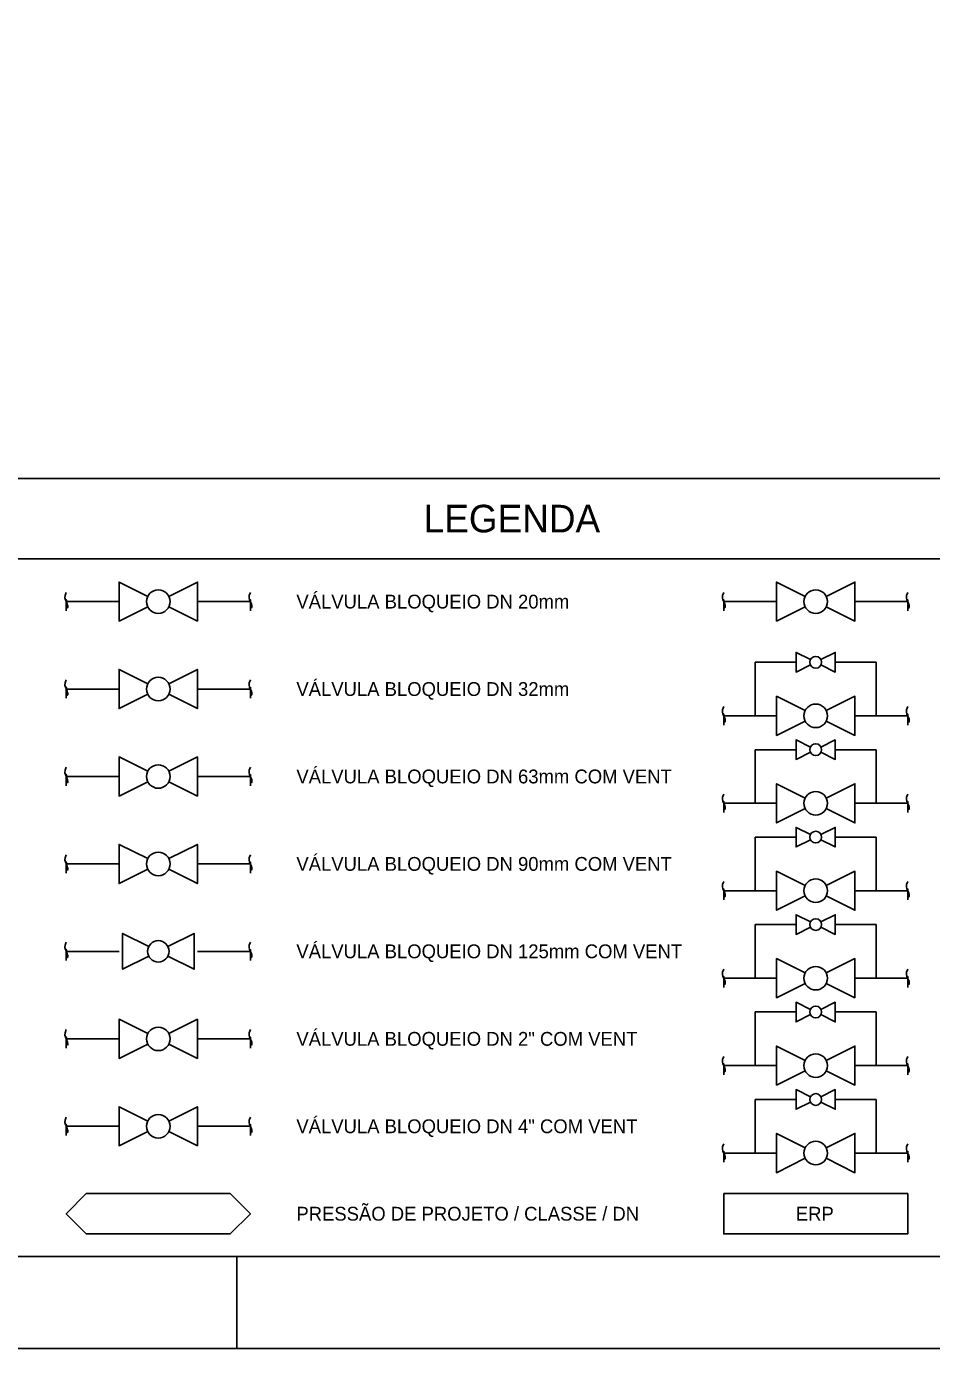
# Model space of a CAD drawing. Extents: x 0 to 841, y 0 to 594.
# Drawn here: x 317.6 to 416, y 0 to 143.7 of the extents above; entities that cross this region are included whole.
import ezdxf

# ---------------------------------------------------------------- set-up
doc = ezdxf.new("R2010")
doc.units = 0
for name, color, linetype in [('FORMATO', 7, 'Continuous'), ('LEGENDA', 7, 'Continuous'), ('MEIO_FIO_GUIA', 7, 'Continuous'), ('SIMBOLO', 7, 'Continuous'), ('VALVULA_ACO_10', 7, 'Continuous'), ('VALVULA_ACO_12', 7, 'Continuous'), ('VALVULA_ACO_14', 7, 'Continuous'), ('VALVULA_ACO_16', 7, 'Continuous'), ('VALVULA_ACO_18', 7, 'Continuous'), ('VALVULA_ACO_2', 7, 'Continuous'), ('VALVULA_ACO_4', 7, 'Continuous'), ('VALVULA_ACO_6', 7, 'Continuous'), ('VALVULA_ACO_8', 7, 'Continuous'), ('VALVULA_PEAD_125', 7, 'Continuous'), ('VALVULA_PEAD_20', 7, 'Continuous'), ('VALVULA_PEAD_32', 7, 'Continuous'), ('VALVULA_PEAD_63', 7, 'Continuous'), ('VALVULA_PEAD_90', 7, 'Continuous')]:
    doc.layers.add(name, color=color, linetype=linetype)

# ---------------------------------------------------------------- blocks, each defined once
blk = doc.blocks.new('VB63')
at = {"layer": 'VALVULA_PEAD_63'}
for points in [[(-1018.223773, 347.405131), (-1021.335533, 345.849251), (-1021.335533, 350.102196), (-1018.223773, 348.546316)], [(-1015.941403, 347.405131), (-1012.829643, 345.849251), (-1012.829643, 350.102196), (-1015.941403, 348.546316)]]:
    blk.add_lwpolyline(points, dxfattribs=at)
blk.add_circle((-1017.082588, 347.975723), 1.275883, dxfattribs=at)
for start, end in [(0, 180), (180, 0)]:
    blk.add_arc((-1017.082588, 347.975723), 1.275883, start, end, dxfattribs=at)
blk = doc.blocks.new('VB125')
at = {"layer": 'VALVULA_PEAD_125'}
for points in [[(-0.347922, -0.173961), (-1.296629, -0.648315), (-1.296629, 0.648315), (-0.347922, 0.173961)], [(0.347922, -0.173961), (1.296629, -0.648315), (1.296629, 0.648315), (0.347922, 0.173961)]]:
    blk.add_lwpolyline(points, dxfattribs=at)
blk.add_circle((0, 0), 0.388989, dxfattribs=at)
for start, end in [(0, 180), (180, 0)]:
    blk.add_arc((0, 0), 0.388989, start, end, dxfattribs=at)
blk = doc.blocks.new('VB DN2')
at = {"layer": 'VALVULA_ACO_2'}
for points in [[(-1.141185, -0.570592), (-4.252945, -2.126472), (-4.252945, 2.126472), (-1.141185, 0.570592)], [(1.141185, -0.570592), (4.252945, -2.126472), (4.252945, 2.126472), (1.141185, 0.570592)]]:
    blk.add_lwpolyline(points, dxfattribs=at)
blk.add_circle((0, 0), 1.275883, dxfattribs=at)
for start, end in [(0, 180), (180, 0)]:
    blk.add_arc((0, 0), 1.275883, start, end, dxfattribs=at)

msp = doc.modelspace()

# ---------------------------------------------------------------- linework, layer by layer
at = {"layer": 'FORMATO'}
for p, q in [((831.01, 94.54), (25, 94.54)), ((25, 85.81), (656, 85.81)), ((831.01, 10), (5, 10)), ((340.5, 0), (340.5, 10))]:
    msp.add_line(p, q, dxfattribs=at)
msp.add_lwpolyline([(0, 594), (841, 594), (841, 0), (0, 0)], close=True, dxfattribs=at)
at = {"layer": 'LEGENDA'}
for points in [[(324.15, 16.84), (339.78, 16.84), (341.97, 14.65), (341.97, 14.65), (339.78, 12.46), (324.15, 12.46), (321.97, 14.65), (321.97, 14.65)], [(393.39, 16.84), (413.39, 16.84), (413.39, 12.46), (393.39, 12.46)]]:
    msp.add_lwpolyline(points, close=True, dxfattribs=at)
at = {"layer": 'MEIO_FIO_GUIA'}
msp.add_lwpolyline([(25, 584), (25, 94.54), (572.92, 94.54), (831.01, 94.54), (831.01, 251.27), (831.01, 584)], close=True, dxfattribs=at)
at = {"layer": 'VALVULA_ACO_10'}
for p, q in [((396.82, 65.07), (401.26, 65.07)), ((396.82, 59.25), (396.82, 65.07)), ((405.51, 65.07), (409.96, 65.07)), ((409.96, 59.25), (409.96, 65.07)), ((393.39, 59.25), (399.13, 59.25)), ((407.64, 59.25), (413.39, 59.25))]:
    msp.add_line(p, q, dxfattribs=at)
for points in [[(402.82, 64.79), (401.26, 64.01), (401.26, 66.13), (402.82, 65.36)], [(403.96, 64.79), (405.51, 64.01), (405.51, 66.13), (403.96, 65.36)], [(402.24, 58.68), (399.13, 57.12), (399.13, 61.37), (402.24, 59.82)], [(404.53, 58.68), (407.64, 57.12), (407.64, 61.37), (404.53, 59.82)]]:
    msp.add_lwpolyline(points, dxfattribs=at)
for centre, radius in [((403.39, 65.07), 0.638), ((403.39, 59.25), 1.28)]:
    msp.add_circle(centre, radius, dxfattribs=at)
for centre, radius, start, end in [((403.39, 65.07), 0.638, 0, 180), ((403.39, 65.07), 0.638, 180, 0), ((403.39, 59.25), 1.28, 0, 180), ((403.39, 59.25), 1.28, 180, 0)]:
    msp.add_arc(centre, radius, start, end, dxfattribs=at)
for points in [[(393.39, 60.25), (393.14, 59.75), (393.39, 59.25), (393.64, 58.75), (393.39, 58.25), (393.39, 60.25), (393.39, 58.25)], [(413.39, 60.25), (413.14, 59.75), (413.39, 59.25), (413.64, 58.75), (413.39, 58.25), (413.39, 60.25), (413.39, 58.25)]]:
    msp.add_open_spline(points, degree=3, dxfattribs=at)
at = {"layer": 'VALVULA_ACO_12'}
for p, q in [((396.82, 55.57), (401.26, 55.57)), ((396.82, 49.75), (396.82, 55.57)), ((405.51, 55.57), (409.96, 55.57)), ((409.96, 49.75), (409.96, 55.57)), ((393.39, 49.75), (399.13, 49.75)), ((407.64, 49.75), (413.39, 49.75))]:
    msp.add_line(p, q, dxfattribs=at)
for points in [[(402.82, 55.28), (401.26, 54.51), (401.26, 56.63), (402.82, 55.85)], [(403.96, 55.28), (405.51, 54.51), (405.51, 56.63), (403.96, 55.85)], [(402.24, 49.18), (399.13, 47.62), (399.13, 51.87), (402.24, 50.32)], [(404.53, 49.18), (407.64, 47.62), (407.64, 51.87), (404.53, 50.32)]]:
    msp.add_lwpolyline(points, dxfattribs=at)
for centre, radius in [((403.39, 55.57), 0.638), ((403.39, 49.75), 1.28)]:
    msp.add_circle(centre, radius, dxfattribs=at)
for centre, radius, start, end in [((403.39, 55.57), 0.638, 0, 180), ((403.39, 55.57), 0.638, 180, 0), ((403.39, 49.75), 1.28, 0, 180), ((403.39, 49.75), 1.28, 180, 0)]:
    msp.add_arc(centre, radius, start, end, dxfattribs=at)
for points in [[(393.39, 50.75), (393.14, 50.25), (393.39, 49.75), (393.64, 49.25), (393.39, 48.75), (393.39, 50.75), (393.39, 48.75)], [(413.39, 50.75), (413.14, 50.25), (413.39, 49.75), (413.64, 49.25), (413.39, 48.75), (413.39, 50.75), (413.39, 48.75)]]:
    msp.add_open_spline(points, degree=3, dxfattribs=at)
at = {"layer": 'VALVULA_ACO_14'}
for p, q in [((396.82, 46.07), (401.26, 46.07)), ((396.82, 40.24), (396.82, 46.07)), ((405.51, 46.07), (409.96, 46.07)), ((409.96, 40.24), (409.96, 46.07)), ((393.39, 40.24), (399.13, 40.24)), ((407.64, 40.24), (413.39, 40.24))]:
    msp.add_line(p, q, dxfattribs=at)
for points in [[(402.82, 45.78), (401.26, 45), (401.26, 47.13), (402.82, 46.35)], [(403.96, 45.78), (405.51, 45), (405.51, 47.13), (403.96, 46.35)], [(402.24, 39.67), (399.13, 38.12), (399.13, 42.37), (402.24, 40.82)], [(404.53, 39.67), (407.64, 38.12), (407.64, 42.37), (404.53, 40.82)]]:
    msp.add_lwpolyline(points, dxfattribs=at)
for centre, radius in [((403.39, 46.07), 0.638), ((403.39, 40.24), 1.28)]:
    msp.add_circle(centre, radius, dxfattribs=at)
for centre, radius, start, end in [((403.39, 46.07), 0.638, 0, 180), ((403.39, 46.07), 0.638, 180, 0), ((403.39, 40.24), 1.28, 0, 180), ((403.39, 40.24), 1.28, 180, 0)]:
    msp.add_arc(centre, radius, start, end, dxfattribs=at)
for points in [[(393.39, 41.24), (393.14, 40.74), (393.39, 40.24), (393.64, 39.74), (393.39, 39.24), (393.39, 41.24), (393.39, 39.24)], [(413.39, 41.24), (413.14, 40.74), (413.39, 40.24), (413.64, 39.74), (413.39, 39.24), (413.39, 41.24), (413.39, 39.24)]]:
    msp.add_open_spline(points, degree=3, dxfattribs=at)
at = {"layer": 'VALVULA_ACO_16'}
for p, q in [((396.82, 36.57), (401.26, 36.57)), ((396.82, 30.74), (396.82, 36.57)), ((405.51, 36.57), (409.96, 36.57)), ((409.96, 30.74), (409.96, 36.57)), ((393.39, 30.74), (399.13, 30.74)), ((407.64, 30.74), (413.39, 30.74))]:
    msp.add_line(p, q, dxfattribs=at)
for points in [[(402.82, 36.28), (401.26, 35.5), (401.26, 37.63), (402.82, 36.85)], [(403.96, 36.28), (405.51, 35.5), (405.51, 37.63), (403.96, 36.85)], [(402.24, 30.17), (399.13, 28.62), (399.13, 32.87), (402.24, 31.31)], [(404.53, 30.17), (407.64, 28.62), (407.64, 32.87), (404.53, 31.31)]]:
    msp.add_lwpolyline(points, dxfattribs=at)
for centre, radius in [((403.39, 36.57), 0.638), ((403.39, 30.74), 1.28)]:
    msp.add_circle(centre, radius, dxfattribs=at)
for centre, radius, start, end in [((403.39, 36.57), 0.638, 0, 180), ((403.39, 36.57), 0.638, 180, 0), ((403.39, 30.74), 1.28, 0, 180), ((403.39, 30.74), 1.28, 180, 0)]:
    msp.add_arc(centre, radius, start, end, dxfattribs=at)
for points in [[(393.39, 31.74), (393.14, 31.24), (393.39, 30.74), (393.64, 30.24), (393.39, 29.74), (393.39, 31.74), (393.39, 29.74)], [(413.39, 31.74), (413.14, 31.24), (413.39, 30.74), (413.64, 30.24), (413.39, 29.74), (413.39, 31.74), (413.39, 29.74)]]:
    msp.add_open_spline(points, degree=3, dxfattribs=at)
at = {"layer": 'VALVULA_ACO_18'}
for p, q in [((396.82, 27.06), (401.26, 27.06)), ((396.82, 21.24), (396.82, 27.06)), ((405.51, 27.06), (409.96, 27.06)), ((409.96, 21.24), (409.96, 27.06)), ((393.39, 21.24), (399.13, 21.24)), ((407.64, 21.24), (413.39, 21.24))]:
    msp.add_line(p, q, dxfattribs=at)
for points in [[(402.82, 26.78), (401.26, 26), (401.26, 28.13), (402.82, 27.35)], [(403.96, 26.78), (405.51, 26), (405.51, 28.13), (403.96, 27.35)], [(402.24, 20.67), (399.13, 19.11), (399.13, 23.37), (402.24, 21.81)], [(404.53, 20.67), (407.64, 19.11), (407.64, 23.37), (404.53, 21.81)]]:
    msp.add_lwpolyline(points, dxfattribs=at)
for centre, radius in [((403.39, 27.06), 0.638), ((403.39, 21.24), 1.28)]:
    msp.add_circle(centre, radius, dxfattribs=at)
for centre, radius, start, end in [((403.39, 27.06), 0.638, 0, 180), ((403.39, 27.06), 0.638, 180, 0), ((403.39, 21.24), 1.28, 0, 180), ((403.39, 21.24), 1.28, 180, 0)]:
    msp.add_arc(centre, radius, start, end, dxfattribs=at)
for points in [[(393.39, 22.24), (393.14, 21.74), (393.39, 21.24), (393.64, 20.74), (393.39, 20.24), (393.39, 22.24), (393.39, 20.24)], [(413.39, 22.24), (413.14, 21.74), (413.39, 21.24), (413.64, 20.74), (413.39, 20.24), (413.39, 22.24), (413.39, 20.24)]]:
    msp.add_open_spline(points, degree=3, dxfattribs=at)
at = {"layer": 'VALVULA_ACO_2'}
for p, q in [((321.97, 33.65), (327.71, 33.65)), ((336.22, 33.65), (341.97, 33.65))]:
    msp.add_line(p, q, dxfattribs=at)
for points in [[(321.97, 34.65), (321.72, 34.15), (321.97, 33.65), (322.22, 33.15), (321.97, 32.65), (321.97, 34.65), (321.97, 32.65)], [(341.97, 34.65), (341.72, 34.15), (341.97, 33.65), (342.22, 33.15), (341.97, 32.65), (341.97, 34.65), (341.97, 32.65)]]:
    msp.add_open_spline(points, degree=3, dxfattribs=at)
at = {"layer": 'VALVULA_ACO_4'}
for p, q in [((321.97, 24.15), (327.71, 24.15)), ((336.22, 24.15), (341.97, 24.15))]:
    msp.add_line(p, q, dxfattribs=at)
for points in [[(330.83, 23.58), (327.71, 22.03), (327.71, 26.28), (330.83, 24.72)], [(333.11, 23.58), (336.22, 22.03), (336.22, 26.28), (333.11, 24.72)]]:
    msp.add_lwpolyline(points, dxfattribs=at)
msp.add_circle((331.97, 24.15), 1.28, dxfattribs=at)
for start, end in [(0, 180), (180, 0)]:
    msp.add_arc((331.97, 24.15), 1.28, start, end, dxfattribs=at)
for points in [[(321.97, 25.15), (321.72, 24.65), (321.97, 24.15), (322.22, 23.65), (321.97, 23.15), (321.97, 25.15), (321.97, 23.15)], [(341.97, 25.15), (341.72, 24.65), (341.97, 24.15), (342.22, 23.65), (341.97, 23.15), (341.97, 25.15), (341.97, 23.15)]]:
    msp.add_open_spline(points, degree=3, dxfattribs=at)
at = {"layer": 'VALVULA_ACO_6'}
for p, q in [((393.39, 81.16), (399.13, 81.16)), ((407.64, 81.16), (413.39, 81.16))]:
    msp.add_line(p, q, dxfattribs=at)
for points in [[(402.24, 80.59), (399.13, 79.04), (399.13, 83.29), (402.24, 81.73)], [(404.53, 80.59), (407.64, 79.04), (407.64, 83.29), (404.53, 81.73)]]:
    msp.add_lwpolyline(points, dxfattribs=at)
msp.add_circle((403.39, 81.16), 1.28, dxfattribs=at)
for start, end in [(0, 180), (180, 0)]:
    msp.add_arc((403.39, 81.16), 1.28, start, end, dxfattribs=at)
for points in [[(393.39, 82.16), (393.14, 81.66), (393.39, 81.16), (393.64, 80.66), (393.39, 80.16), (393.39, 82.16), (393.39, 80.16)], [(413.39, 82.16), (413.14, 81.66), (413.39, 81.16), (413.64, 80.66), (413.39, 80.16), (413.39, 82.16), (413.39, 80.16)]]:
    msp.add_open_spline(points, degree=3, dxfattribs=at)
at = {"layer": 'VALVULA_ACO_8'}
for p, q in [((396.82, 74.57), (401.26, 74.57)), ((396.82, 68.75), (396.82, 74.57)), ((405.51, 74.57), (409.96, 74.57)), ((409.96, 68.75), (409.96, 74.57)), ((393.39, 68.75), (399.13, 68.75)), ((407.64, 68.75), (413.39, 68.75))]:
    msp.add_line(p, q, dxfattribs=at)
for points in [[(402.82, 74.29), (401.26, 73.51), (401.26, 75.64), (402.82, 74.86)], [(403.96, 74.29), (405.51, 73.51), (405.51, 75.64), (403.96, 74.86)], [(402.24, 68.18), (399.13, 66.62), (399.13, 70.88), (402.24, 69.32)], [(404.53, 68.18), (407.64, 66.62), (407.64, 70.88), (404.53, 69.32)]]:
    msp.add_lwpolyline(points, dxfattribs=at)
for centre, radius in [((403.39, 74.57), 0.638), ((403.39, 68.75), 1.28)]:
    msp.add_circle(centre, radius, dxfattribs=at)
for centre, radius, start, end in [((403.39, 74.57), 0.638, 0, 180), ((403.39, 74.57), 0.638, 180, 0), ((403.39, 68.75), 1.28, 0, 180), ((403.39, 68.75), 1.28, 180, 0)]:
    msp.add_arc(centre, radius, start, end, dxfattribs=at)
for points in [[(393.39, 69.75), (393.14, 69.25), (393.39, 68.75), (393.64, 68.25), (393.39, 67.75), (393.39, 69.75), (393.39, 67.75)], [(413.39, 69.75), (413.14, 69.25), (413.39, 68.75), (413.64, 68.25), (413.39, 67.75), (413.39, 69.75), (413.39, 67.75)]]:
    msp.add_open_spline(points, degree=3, dxfattribs=at)
at = {"layer": 'VALVULA_PEAD_125'}
for p, q in [((321.97, 43.16), (327.71, 43.16)), ((336.22, 43.16), (341.97, 43.16))]:
    msp.add_line(p, q, dxfattribs=at)
for points in [[(321.97, 44.16), (321.72, 43.66), (321.97, 43.16), (322.22, 42.66), (321.97, 42.16), (321.97, 44.16), (321.97, 42.16)], [(341.97, 44.16), (341.72, 43.66), (341.97, 43.16), (342.22, 42.66), (341.97, 42.16), (341.97, 44.16), (341.97, 42.16)]]:
    msp.add_open_spline(points, degree=3, dxfattribs=at)
at = {"layer": 'VALVULA_PEAD_20'}
for p, q in [((321.97, 81.16), (327.71, 81.16)), ((336.22, 81.16), (341.97, 81.16))]:
    msp.add_line(p, q, dxfattribs=at)
for points in [[(330.83, 80.59), (327.71, 79.04), (327.71, 83.29), (330.83, 81.73)], [(333.11, 80.59), (336.22, 79.04), (336.22, 83.29), (333.11, 81.73)]]:
    msp.add_lwpolyline(points, dxfattribs=at)
msp.add_circle((331.97, 81.16), 1.28, dxfattribs=at)
for start, end in [(0, 180), (180, 0)]:
    msp.add_arc((331.97, 81.16), 1.28, start, end, dxfattribs=at)
for points in [[(321.97, 82.16), (321.72, 81.66), (321.97, 81.16), (322.22, 80.66), (321.97, 80.16), (321.97, 82.16), (321.97, 80.16)], [(341.97, 82.16), (341.72, 81.66), (341.97, 81.16), (342.22, 80.66), (341.97, 80.16), (341.97, 82.16), (341.97, 80.16)]]:
    msp.add_open_spline(points, degree=3, dxfattribs=at)
at = {"layer": 'VALVULA_PEAD_32'}
for p, q in [((321.97, 71.66), (327.71, 71.66)), ((336.22, 71.66), (341.97, 71.66))]:
    msp.add_line(p, q, dxfattribs=at)
for points in [[(330.83, 71.09), (327.71, 69.53), (327.71, 73.79), (330.83, 72.23)], [(333.11, 71.09), (336.22, 69.53), (336.22, 73.79), (333.11, 72.23)]]:
    msp.add_lwpolyline(points, dxfattribs=at)
msp.add_circle((331.97, 71.66), 1.28, dxfattribs=at)
for start, end in [(0, 180), (180, 0)]:
    msp.add_arc((331.97, 71.66), 1.28, start, end, dxfattribs=at)
for points in [[(321.97, 72.66), (321.72, 72.16), (321.97, 71.66), (322.22, 71.16), (321.97, 70.66), (321.97, 72.66), (321.97, 70.66)], [(341.97, 72.66), (341.72, 72.16), (341.97, 71.66), (342.22, 71.16), (341.97, 70.66), (341.97, 72.66), (341.97, 70.66)]]:
    msp.add_open_spline(points, degree=3, dxfattribs=at)
at = {"layer": 'VALVULA_PEAD_63'}
for p, q in [((321.97, 62.16), (327.71, 62.16)), ((336.22, 62.16), (341.97, 62.16))]:
    msp.add_line(p, q, dxfattribs=at)
for points in [[(321.97, 63.16), (321.72, 62.66), (321.97, 62.16), (322.22, 61.66), (321.97, 61.16), (321.97, 63.16), (321.97, 61.16)], [(341.97, 63.16), (341.72, 62.66), (341.97, 62.16), (342.22, 61.66), (341.97, 61.16), (341.97, 63.16), (341.97, 61.16)]]:
    msp.add_open_spline(points, degree=3, dxfattribs=at)
at = {"layer": 'VALVULA_PEAD_90'}
for p, q in [((321.97, 52.66), (327.71, 52.66)), ((336.22, 52.66), (341.97, 52.66))]:
    msp.add_line(p, q, dxfattribs=at)
for points in [[(330.83, 52.09), (327.71, 50.53), (327.71, 54.78), (330.83, 53.23)], [(333.11, 52.09), (336.22, 50.53), (336.22, 54.78), (333.11, 53.23)]]:
    msp.add_lwpolyline(points, dxfattribs=at)
msp.add_circle((331.97, 52.66), 1.28, dxfattribs=at)
for start, end in [(0, 180), (180, 0)]:
    msp.add_arc((331.97, 52.66), 1.28, start, end, dxfattribs=at)
for points in [[(321.97, 53.66), (321.72, 53.16), (321.97, 52.66), (322.22, 52.16), (321.97, 51.66), (321.97, 53.66), (321.97, 51.66)], [(341.97, 53.66), (341.72, 53.16), (341.97, 52.66), (342.22, 52.16), (341.97, 51.66), (341.97, 53.66), (341.97, 51.66)]]:
    msp.add_open_spline(points, degree=3, dxfattribs=at)

# ---------------------------------------------------------------- block references
at = {"layer": 'SIMBOLO'}
for name, p in [('VB63', (1349.05, -285.82)), ('VB DN2', (331.97, 33.65))]:
    msp.add_blockref(name, p, dxfattribs=at)
at = {"layer": 'SIMBOLO', "xscale": 3, "yscale": 3}
msp.add_blockref('VB125', (331.97, 43.16), dxfattribs=at)

# ---------------------------------------------------------------- texts
at = {"layer": 'FORMATO'}
msp.add_text('LEGENDA', height=3, rotation=360, dxfattribs=at).set_placement((360.8, 88.68))
at = {"layer": 'LEGENDA'}
for s, p in [('VÁLVULA BLOQUEIO DN 20mm', (346.97, 80.41)), ('VÁLVULA BLOQUEIO DN 32mm', (346.97, 70.91)), ('VÁLVULA BLOQUEIO DN 63mm COM VENT', (346.97, 61.41)), ('VÁLVULA BLOQUEIO DN 90mm COM VENT', (346.97, 51.91)), ('VÁLVULA BLOQUEIO DN 125mm COM VENT', (346.97, 42.41)), ('VÁLVULA BLOQUEIO DN 2" COM VENT', (346.97, 32.9)), ('VÁLVULA BLOQUEIO DN 4" COM VENT', (346.97, 23.4)), ('PRESSÃO DE PROJETO / CLASSE / DN', (346.97, 13.9)), ('ERP', (401.23, 13.9))]:
    msp.add_text(s, height=1.5, dxfattribs=at).set_placement(p)

doc.saveas('drawing.dxf')
